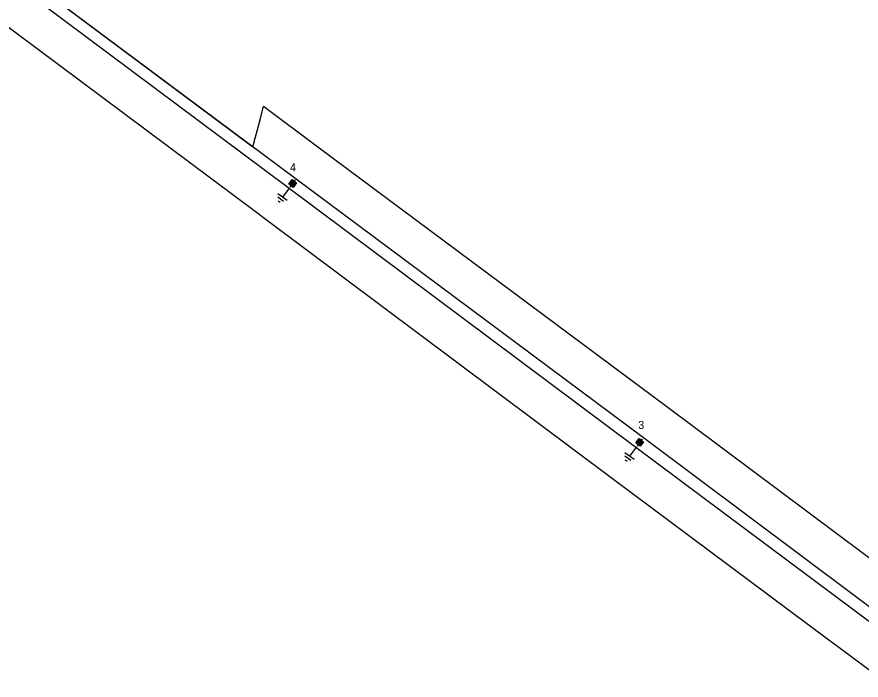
# Model space of a CAD drawing. Extents: x -540879 to -537255, y -1184046 to -1180016.
# Drawn here: x -540294.7 to -540110, y -1183862.1 to -1183717.1 of the extents above; entities that cross this region are included whole.
import ezdxf

# ---------------------------------------------------------------- set-up
doc = ezdxf.new("R2010")
doc.units = 0
for name, color, linetype in [('Vrstva 1', 7, 'Continuous'), ('Vrstva 13', 7, 'Continuous'), ('Vrstva 14', 7, 'Continuous'), ('Vrstva 15', 7, 'Continuous'), ('Vrstva 2', 7, 'Continuous'), ('Vrstva 35', 7, 'Continuous')]:
    doc.layers.add(name, color=color, linetype=linetype)

# ---------------------------------------------------------------- blocks, each defined once
blk = doc.blocks.new('VN810')
at = {"layer": 'Vrstva 14'}
for points in [[(0, -1.25), (0, -3.75)], [(1.25, -3.75), (-1.25, -3.75)], [(0.77, -4.37), (-0.8, -4.37)], [(0, -5), (-0.25, -5)], [(0.27, -5), (0, -5)]]:
    blk.add_lwpolyline(points, dxfattribs=at)
blk = doc.blocks.new('VN470')
at = {"layer": 'Vrstva 2'}
for points in [[(-1.23, 1.22), (1.23, 1.22)], [(-1.23, -1.23), (-1.23, 1.22)], [(-0.92, 0.9), (0.92, 0.9)], [(-0.92, -0.95), (-0.92, 0.9)], [(-0.61, 0.61), (0.61, 0.61)], [(-0.61, -0.62), (-0.61, 0.61)], [(-0.31, -0.27), (-0.31, 0.34)], [(-0.31, 0.34), (0.31, 0.34)], [(0, 1.22), (0, 1.97)], [(0.31, 0.34), (0.31, -0.27)], [(0.61, 0.61), (0.61, -0.62)], [(0.92, 0.9), (0.92, -0.95)], [(1.23, 1.22), (1.23, -1.23)], [(1.23, -1.23), (-1.23, -1.23)], [(0.92, -0.95), (-0.92, -0.95)], [(0.61, -0.62), (-0.61, -0.62)], [(0.31, -0.27), (-0.31, -0.27)], [(0, -1.23), (0, -1.98)]]:
    blk.add_lwpolyline(points, dxfattribs=at)

msp = doc.modelspace()

# ---------------------------------------------------------------- linework, layer by layer
at = {"layer": 'Vrstva 1'}
for points in [[(-540084.14, -1183862.05), (-540101.85, -1183854.04), (-540159.34, -1183811.21), (-540235.1, -1183754.61), (-540318.87, -1183692.12), (-540400.06, -1183631.69), (-540472.76, -1183579.47), (-540603.37, -1183567.42), (-540704.86, -1183559.14), (-540798.66, -1183550.97), (-540879.38, -1183550.59)], [(-540398.69, -1183629.52), (-540317.37, -1183690.09), (-540233.62, -1183752.5), (-540157.62, -1183809.02), (-540100.23, -1183851.93), (-540082.89, -1183854.15)]]:
    msp.add_lwpolyline(points, dxfattribs=at)
at = {"layer": 'Vrstva 35'}
for points in [[(-540317.37, -1183690.09), (-540243.05, -1183745.47), (-540241.44, -1183739.28), (-540240.74, -1183736.59), (-540228.54, -1183745.68), (-540152.54, -1183802.21), (-540096.93, -1183843.78), (-540081.9, -1183845.71), (-540081.85, -1183845.71), (-540081.81, -1183845.72), (-540076.43, -1183846.35), (-540073.37, -1183821.78), (-540073.27, -1183820.77), (-540073.21, -1183820.31), (-540066.7, -1183765.76), (-540055.3, -1183656.87)], [(-540107.43, -1183860.48), (-540113.21, -1183856.18), (-540117.37, -1183853.08), (-540164.42, -1183818.03), (-540240.19, -1183761.42), (-540242.31, -1183759.84), (-540323.95, -1183698.93)]]:
    msp.add_lwpolyline(points, dxfattribs=at)

# ---------------------------------------------------------------- block references
at = {"layer": 'Vrstva 13', "xscale": 0.5, "yscale": 0.5}
for p, rotation in [((-540234.36, -1183753.49), -36.7039722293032), ((-540158.45, -1183810.09), -36.67322223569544)]:
    msp.add_blockref('VN470', p, dxfattribs=dict(at, rotation=rotation))
at = {"layer": 'Vrstva 15'}
for p, rotation in [((-540234.36, -1183753.49), -36.70393895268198), ((-540158.44, -1183810.09), -36.70430563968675)]:
    msp.add_blockref('VN810', p, dxfattribs=dict(at, rotation=rotation))

# ---------------------------------------------------------------- texts
at = {"layer": 'Vrstva 14'}
for s, p in [('4', (-540234.96, -1183750.85)), ('3', (-540158.78, -1183807.15))]:
    msp.add_text(s, height=1.75, dxfattribs=at).set_placement(p)

doc.saveas('drawing.dxf')
